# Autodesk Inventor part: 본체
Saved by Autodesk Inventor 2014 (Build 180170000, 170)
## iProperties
Created: 2026-06
Part Number: 본체
Material: 일반
Document SubType Name: Modeling
Designer: dg
Density: 1 g/cm^3
Appearance: 기본값
Author: dg
Author: jhkim
Creation Date: 2026-05-29
Sending System: Autodesk Inventor 2027
Preprocessor: ST-DEVELOPER v20.1
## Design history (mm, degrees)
node "본체1"
node "솔리드1"
node "기준1"
